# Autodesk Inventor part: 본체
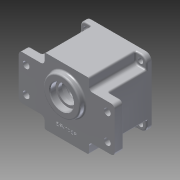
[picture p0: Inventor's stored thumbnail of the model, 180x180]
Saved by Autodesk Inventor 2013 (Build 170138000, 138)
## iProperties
Created: 2015-07
Part Number: 본체
Material: 알루미늄 6061
Document SubType Name: Modeling
Designer: user
Density: 2.71 g/cm^3
Mass: 700.948 g
Surface Area: 679.373 cm^2
Volume: 258.652 cm^3
Author: user
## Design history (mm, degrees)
sketch "스케치1"
  geometry: L1 (65, -30)-(65, 30); L2 (-65, 30)-(-65, -30); L3 (-30, 45)-(30, 45); L4 (30, -45)-(-30, -45); L5 (65, 30)-(35, 30); L6 (-35, 30)-(-65, 30); L7 (30, 45)-(30, 35); L8 (30, -35)-(30, -45); L9 (-30, -45)-(-30, -35); L10 (-30, 35)-(-30, 45); L11 (-65, -30)-(-35, -30); L12 (35, -30)-(65, -30); A1 r 5 centre (35, 35) between (30, 35) and (35, 30); A2 r 5 centre (35, -35) between (35, -30) and (30, -35); A3 r 5 centre (-35, -35) between (-30, -35) and (-35, -30); A4 r 5 centre (-35, 35) between (-35, 30) and (-30, 35); 5 further points
  constraints: 24 end point, 12 tangent, 10 parallel, 8 point on circle, 4 centre point, 4 perpendicular, 3 equal radius, 3 horizontal, 2 horizontal alignment, 2 midpoint, 2 vertical alignment
  dimensions: "d0" = 130 distance of L1.end L2.start; "d2" = 60 distance of L2.start L2.end; "d3" = 60 distance of L3.start L3.end; "d4" = 90 distance of L3.end L4.start; "d5" = 5 radius of A1; "d6" = 35 distance between parallel lines of L1 L8; "d7" = 75 distance between parallel lines of L5 L4; "d8" = 35 distance from line of point (30, 0) L1; "d9" = 60 distance from line of point (0, -30) L5
extrude "돌출1" new body sketch "스케치1" distance "d10" = 12; taper "d11" = 0 deg
sketch "스케치2"
  geometry: L1 (-45, -45)-(45, -45); L2 (45, -45)-(45, 45); L3 (45, 45)-(-45, 45); L4 (-45, 45)-(-45, -45); 3 further points
  constraints: 8 end point, 2 midpoint, 2 parallel, 1 horizontal, 1 horizontal alignment, 1 perpendicular, 1 vertical alignment
  dimensions: "d12" = 90 distance of L3.end L2.end; "d13" = 90 distance of L2.end L1.end
extrude "돌출2" join sketch "스케치2" distance "d14" = 58; taper "d15" = 0 deg
sketch "스케치3"
  geometry: L1 (35, 30)-(45, 30) reference; L2 (45, 45)-(45, 30) reference; L3 (35, 30)-(45, 30) reference; L4 (30, 45)-(30, 35) reference; L5 (-30, 45)-(30, 45) reference; L6 (-30, 35)-(-30, 45) reference; L7 (-45, 30)-(-35, 30) reference; L8 (-45, -30)-(-45, 30) reference; L9 (-45, -30)-(-65, -30) reference; L10 (-65, -30)-(-65, 30) reference; L11 (-65, 30)-(-45, 30) reference; L12 (-45, 30)-(-45, 45) reference; L13 (-45, 45)-(-30, 45) reference; L14 (30, 45)-(45, 45) reference; L15 (45, 30)-(45, -30) reference; L16 (65, -30)-(45, -30) reference; L17 (65, 30)-(65, -30) reference; L18 (45, 30)-(65, 30) reference; L19 (-45, -45)-(-45, -30) reference; L20 (-35, -30)-(-45, -30) reference; L21 (-30, -45)-(-30, -35) reference; L22 (-30, -45)-(-45, -45) reference; L23 (45, -30)-(45, -45) reference; L24 (45, -45)-(30, -45) reference; L25 (30, -45)-(-30, -45) reference; L26 (45, -30)-(35, -30) reference; L27 (30, -35)-(30, -45) reference; A1 r 5 centre (35, 35) between (30, 35) and (35, 30) reference; A2 r 5 centre (-35, 35) between (-35, 30) and (-30, 35) reference; A3 r 5 centre (-35, -35) between (-30, -35) and (-35, -30) reference; A4 r 5 centre (35, -35) between (35, -30) and (30, -35) reference; 1 further point
extrude "돌출3" cut sketch "스케치3" distance "d16" = 51; taper "d17" = 0 deg
sketch "스케치4"
  geometry: L1 (60, 0)-(60, 63) reference; L2 (60, 63)-(75, 63) reference; L3 (75, 63)-(75, 70) reference; L4 (-15, 70)-(75, 70) reference; L5 (-15, 63)-(-15, 70) reference; L6 (-15, 63)-(0, 63) reference; L7 (0, 0)-(0, 63) reference; L8 (60, 0)-(0, 0) reference; 1 further point
fillet "모깎기1" dims "d18" = 8
fillet "모깎기2" dims "d19" = 5
sketch "스케치5"
  geometry: L1 (65, -25)-(65, 25) reference; L2 (60, 30)-(35, 30) reference; C1 r 4.5 at (55, 17.5); C2 r 4.5 at (-55, 17.5); C3 r 4.5 at (55, -17.5); C4 r 4.5 at (-55, -17.5); 1 further point
  constraints: 4 centre point, 3 equal radius
  dimensions: "d26" = 9 diameter of C1; "d27" = 10 distance from line of C1.centre L1; "d28" = 12.5 distance from line of C1.centre L2; "d29" = 10 distance from line of C3.centre L1; "d30" = 47.5 distance from line of C3.centre L2; "d31" = 120 distance from line of C2.centre L1; "d32" = 12.5 distance from line of C2.centre L2; "d33" = 120 distance from line of C4.centre L1; "d34" = 47.5 distance from line of C4.centre L2
extrude "돌출4" cut sketch "스케치5" stored distance "d35" = 51; taper "d36" = 0 deg
sketch "스케치6"
  geometry: L1 (-30, -35)-(-30, -45) reference; L2 (0, 0)-(0, 11); C1 r 25 at (0, 11); 1 further point
  constraints: 2 end point, 1 centre point, 1 coincident, 1 parallel
  dimensions: "d37" = 11 distance of L2.start L2.end; "d38" = 50 diameter of C1
extrude "돌출5" join sketch "스케치6" distance "d39" = 7; taper "d40" = 0 deg
fillet "모깎기4" dims "d41" = 2
sketch "스케치7"
  geometry: C1 r 23 at (0, 0) reference; 1 further point
hole "구멍1" sketch "스케치7" at (0, 0) diameter "d42" = 25; stored, may be unused: countersink angle "d46" = 90 deg, drill point angle "d48" = 118 deg; dims "d43" = 6, "d44" = 32, "d45" = 8, "d47" = 8
chamfer "모따기1" distance "d49" = 1; stored, may be unused: second distance "d50" = 2, angle "d51" = 45 deg
fillet "모깎기5" dims "d52" = 0.3
fillet "모깎기8" dims "d55" = 2
sketch "스케치8"
  geometry: C1 r 3.5 at (-37, -37); C2 r 3.5 at (37, -37); C3 r 3.5 at (37, 37); C4 r 3.5 at (-37, 37); A1 r 8 centre (-37, 37) between (-37, 45) and (-45, 37) reference; A2 r 8 centre (-37, -37) between (-45, -37) and (-37, -45) reference; A3 r 8 centre (37, -37) between (37, -45) and (45, -37) reference; A4 r 8 centre (37, 37) between (45, 37) and (37, 45) reference; 1 further point
  constraints: 4 centre point, 3 concentric, 2 equal radius, 1 coincident
  dimensions: "d65" = 7 diameter of C1; "d66" = 7 diameter of C2
extrude "돌출6" cut sketch "스케치8" stored distance "d67" = 7; taper "d68" = 0 deg
sketch "스케치9"
  geometry: C1 r 12.5 at (0, -11) reference; C2 r 40 at (0, 0); 1 further point
  constraints: 1 centre point, 1 coincident
  dimensions: "d69" = 80 diameter of C2
extrude "돌출7" cut sketch "스케치9" distance "d70" = 9; taper "d71" = 0 deg
sketch "스케치10"
  geometry: C1 r 12.5 at (0, -11) reference; C2 r 40 at (0, 0) reference; C3 r 39 at (0, 0)
  constraints: 1 centre point, 1 coincident
  dimensions: "d72" = 78 diameter of C3
extrude "돌출8" cut sketch "스케치10" distance "d73" = 52; taper "d74" = 0 deg
node "작업 평면1"
sketch "스케치11"
  geometry: 1 further point
sketch "스케치12"
  geometry: L1 (0, 0)-(-55.97, -55.97); L2 (0, 0)-(-45, 0); L3 (-30, -45)-(-30, -35) reference; L4 (-35, -30)-(-45, -30) reference; L5 (-45, -30)-(-45, 30) reference; L6 (-45, 30)-(-35, 30) reference; L7 (-30, 35)-(-30, 45) reference; L8 (30, -45)-(-30, -45) reference; L9 (-30, 45)-(30, 45) reference; L10 (30, 45)-(30, 35) reference; L11 (30, -35)-(30, -45) reference; L12 (35, 30)-(45, 30) reference; L13 (45, 30)-(45, -30) reference; L14 (45, -30)-(35, -30) reference; C1 r 39 at (0, 0) reference; C2 r 40 at (0, 0) reference; C3 r 39 at (0, 0) reference; C4 r 40 at (0, 0) reference; C5 r 4 at (24.749, -24.749); C6 r 4 at (24.749, 24.749); C7 r 4 at (-24.749, 24.749); A1 r 4 centre (-24.749, -24.749) between (-21.809, -27.462) and (-27.462, -21.809); A2 r 39 centre (0, 0) between (-21.134, -32.777) and (-32.777, -21.134); A3 r 3.5 centre (-19.238, -29.836) between (-21.809, -27.462) and (-21.134, -32.777); A4 r 3.5 centre (-29.836, -19.238) between (-32.777, -21.134) and (-27.462, -21.809); A5 r 5 centre (-35, -35) between (-30, -35) and (-35, -30) reference; A6 r 5 centre (-35, 35) between (-35, 30) and (-30, 35) reference; A7 r 5 centre (35, 35) between (30, 35) and (35, 30) reference; A8 r 5 centre (35, -35) between (35, -30) and (30, -35) reference
  constraints: 8 point on circle, 7 centre point, 5 tangent, 4 end point, 1 coincident, 1 point on line, 9 other
  dimensions: "d75" = 45 deg angle of L2 L1; "d77" = 8 diameter of A1; "d80" = 360 deg dimension on C1.centre A1.centre (derived); "d83" = 49.49747 distance of C5.centre C6.centre; "d85" = 7 diameter of A3; "d87" = 7 diameter of A4
extrude "돌출9" join sketch "스케치12" stored distance "d88" = 52; taper "d89" = 0 deg
sketch "스케치13"
  geometry: A1 r 4 centre (-24.749, -24.749) between (-21.809, -27.462) and (-27.462, -21.809) reference; A2 r 4 centre (-24.749, 24.749) between (-27.462, 21.809) and (-21.809, 27.462) reference; A3 r 4 centre (24.749, 24.749) between (21.809, 27.462) and (27.462, 21.809) reference; A4 r 4 centre (24.749, -24.749) between (27.462, -21.809) and (21.809, -27.462) reference
hole "구멍2" sketch "스케치13" at (24.749, 24.749), (24.749, -24.749), (-24.749, -24.749), (-24.749, 24.749) diameter "d93" = 3.459; stored, may be unused: countersink angle "d97" = 90 deg, drill point angle "d99" = 118 deg; dims "d94" = 12, "d95" = 32, "d96" = 8, "d98" = 15
sketch "스케치14"
  geometry: L1 (-60, 30)-(-35, 30) reference; L2 (-30, 35)-(-30, 45) reference; L3 (30, 45)-(30, 35) reference; L4 (35, 30)-(60, 30) reference; L5 (65, 25)-(65, -25) reference; L6 (60, -30)-(35, -30) reference; L7 (30, -35)-(30, -45) reference; L8 (-30, -45)-(-30, -35) reference; L9 (-35, -30)-(-60, -30) reference; L10 (-65, -25)-(-65, 25) reference; L11 (30, -45)-(-30, -45) reference; L12 (-30, 45)-(30, 45) reference; C1 r 12.5 at (0, -11) reference; C2 r 12.5 at (0, -11) reference; C3 r 4.5 at (55, 17.5) reference; C4 r 4.5 at (55, -17.5) reference; C5 r 4.5 at (-55, -17.5) reference; C6 r 4.5 at (-55, 17.5) reference; C7 r 20.5 at (0, -11); A1 r 4 centre (-24.749, -24.749) between (-21.809, -27.462) and (-27.462, -21.809) reference; A2 r 3.5 centre (-19.238, -29.836) between (-21.809, -27.462) and (-21.134, -32.777) reference; A3 r 39 centre (0, 0) between (-21.134, -32.777) and (21.134, -32.777) reference; A4 r 3.5 centre (19.238, -29.836) between (21.134, -32.777) and (21.809, -27.462) reference; A5 r 4 centre (24.749, -24.749) between (27.462, -21.809) and (21.809, -27.462) reference; A6 r 3.5 centre (29.836, -19.238) between (27.462, -21.809) and (32.777, -21.134) reference; A7 r 39 centre (0, 0) between (32.777, -21.134) and (32.777, 21.134) reference; A8 r 3.5 centre (29.836, 19.238) between (32.777, 21.134) and (27.462, 21.809) reference; A9 r 4 centre (24.749, 24.749) between (21.809, 27.462) and (27.462, 21.809) reference; A10 r 3.5 centre (19.238, 29.836) between (21.809, 27.462) and (21.134, 32.777) reference; A11 r 39 centre (0, 0) between (21.134, 32.777) and (-21.134, 32.777) reference; A12 r 3.5 centre (-19.238, 29.836) between (-21.134, 32.777) and (-21.809, 27.462) reference; A13 r 4 centre (-24.749, 24.749) between (-27.462, 21.809) and (-21.809, 27.462) reference; A14 r 3.5 centre (-29.836, 19.238) between (-27.462, 21.809) and (-32.777, 21.134) reference; A15 r 39 centre (0, 0) between (-32.777, 21.134) and (-32.777, -21.134) reference; A16 r 3.5 centre (-29.836, -19.238) between (-32.777, -21.134) and (-27.462, -21.809) reference; A17 r 5 centre (-60, 25) between (-60, 30) and (-65, 25) reference; A18 r 5 centre (-35, 35) between (-35, 30) and (-30, 35) reference; A19 r 5 centre (35, 35) between (30, 35) and (35, 30) reference; A20 r 5 centre (60, 25) between (65, 25) and (60, 30) reference; A21 r 5 centre (60, -25) between (60, -30) and (65, -25) reference; A22 r 5 centre (35, -35) between (35, -30) and (30, -35) reference; A23 r 5 centre (-35, -35) between (-30, -35) and (-35, -30) reference; A24 r 5 centre (-60, -25) between (-65, -25) and (-60, -30) reference
  constraints: 1 centre point, 1 coincident
  dimensions: "d100" = 41 diameter of C7
extrude "돌출10" join sketch "스케치14" distance "d101" = 7; taper "d102" = 0 deg
sketch "스케치15"
  geometry: L1 (-60, 30)-(-35, 30) reference; L2 (-30, 35)-(-30, 45) reference; L3 (30, 45)-(30, 35) reference; L4 (35, 30)-(60, 30) reference; L5 (65, 25)-(65, -25) reference; L6 (60, -30)-(35, -30) reference; L7 (30, -35)-(30, -45) reference; L8 (-30, -45)-(-30, -35) reference; L9 (-35, -30)-(-60, -30) reference; L10 (-65, -25)-(-65, 25) reference; L11 (0, 0)-(0, 20); L12 (30, -45)-(-30, -45) reference; L13 (-30, 45)-(30, 45) reference; C1 r 20.5 at (0, -11) reference; C2 r 12.5 at (0, -11) reference; C3 r 4.5 at (55, 17.5) reference; C4 r 4.5 at (55, -17.5) reference; C5 r 4.5 at (-55, -17.5) reference; C6 r 4.5 at (-55, 17.5) reference; C7 r 14 at (0, 20); A1 r 4 centre (-24.749, -24.749) between (-21.809, -27.462) and (-27.462, -21.809) reference; A2 r 3.5 centre (-19.238, -29.836) between (-21.809, -27.462) and (-21.134, -32.777) reference; A3 r 39 centre (0, 0) between (-21.134, -32.777) and (21.134, -32.777) reference; A4 r 3.5 centre (19.238, -29.836) between (21.134, -32.777) and (21.809, -27.462) reference; A5 r 4 centre (24.749, -24.749) between (27.462, -21.809) and (21.809, -27.462) reference; A6 r 3.5 centre (29.836, -19.238) between (27.462, -21.809) and (32.777, -21.134) reference; A7 r 39 centre (0, 0) between (32.777, -21.134) and (32.777, 21.134) reference; A8 r 3.5 centre (29.836, 19.238) between (32.777, 21.134) and (27.462, 21.809) reference; A9 r 4 centre (24.749, 24.749) between (21.809, 27.462) and (27.462, 21.809) reference; A10 r 3.5 centre (19.238, 29.836) between (21.809, 27.462) and (21.134, 32.777) reference; A11 r 39 centre (0, 0) between (21.134, 32.777) and (-21.134, 32.777) reference; A12 r 3.5 centre (-19.238, 29.836) between (-21.134, 32.777) and (-21.809, 27.462) reference; A13 r 4 centre (-24.749, 24.749) between (-27.462, 21.809) and (-21.809, 27.462) reference; A14 r 3.5 centre (-29.836, 19.238) between (-27.462, 21.809) and (-32.777, 21.134) reference; A15 r 39 centre (0, 0) between (-32.777, 21.134) and (-32.777, -21.134) reference; A16 r 3.5 centre (-29.836, -19.238) between (-32.777, -21.134) and (-27.462, -21.809) reference; A17 r 5 centre (-60, 25) between (-60, 30) and (-65, 25) reference; A18 r 5 centre (-35, 35) between (-35, 30) and (-30, 35) reference; A19 r 5 centre (35, 35) between (30, 35) and (35, 30) reference; A20 r 5 centre (60, 25) between (65, 25) and (60, 30) reference; A21 r 5 centre (60, -25) between (60, -30) and (65, -25) reference; A22 r 5 centre (35, -35) between (35, -30) and (30, -35) reference; A23 r 5 centre (-35, -35) between (-30, -35) and (-35, -30) reference; A24 r 5 centre (-60, -25) between (-65, -25) and (-60, -30) reference
  constraints: 2 end point, 1 centre point, 1 coincident, 1 parallel
  dimensions: "d103" = 20 distance of L11.start L11.end; "d104" = 28 diameter of C7
extrude "돌출11" join sketch "스케치15" distance "d105" = 7; taper "d106" = 0 deg
fillet "모깎기9" dims "d107" = 3
fillet "모깎기10" dims "d108" = 2
fillet "모깎기11" dims "d109" = 2
sketch "스케치16"
  geometry: C1 r 12.5 at (0, -11) reference; A1 r 20.5 centre (0, -11) between (-11.115, 6.225) and (11.115, 6.225) reference; A2 r 3 centre (12.742, 8.746) between (10.493, 10.732) and (11.115, 6.225) reference; A3 r 14 centre (0, 20) between (10.493, 10.732) and (-10.493, 10.732) reference; A4 r 3 centre (-12.742, 8.746) between (-11.115, 6.225) and (-10.493, 10.732) reference; 1 further point
sketch "스케치17"
  geometry: A1 r 20.5 centre (0, -11) between (-11.115, 6.225) and (11.115, 6.225) reference; 1 further point
hole "구멍3" sketch "스케치17" at (0, -11) diameter "d110" = 25; stored, may be unused: countersink angle "d114" = 90 deg, drill point angle "d116" = 118 deg; dims "d111" = 6, "d112" = 35, "d113" = 10, "d115" = 8
fillet "모깎기12" dims "d117" = 0.3
chamfer "모따기2" distance "d118" = 1; stored, may be unused: second distance "d119" = 2, angle "d120" = 45 deg
sketch "스케치18"
  geometry: A1 r 14 centre (0, 20) between (10.493, 10.732) and (-10.493, 10.732) reference; 1 further point
hole "구멍4" sketch "스케치18" at (0, 20) diameter "d121" = 22; stored, may be unused: countersink angle "d125" = 90 deg, drill point angle "d127" = 0 deg; dims "d122" = 6, "d123" = 35, "d124" = 10, "d126" = 7
sketch "스케치19"
  geometry: C1 r 11 at (0, 0) reference; 1 further point
hole "구멍5" sketch "스케치19" at (0, 0) diameter "d128" = 19; stored, may be unused: countersink angle "d132" = 90 deg, drill point angle "d134" = 0 deg; dims "d129" = 6, "d130" = 35, "d131" = 10, "d133" = 1
fillet "모깎기13" dims "d135" = 1
sketch "스케치20"
  geometry: 1 further point
chamfer "모따기3" distance "d136" = 1; stored, may be unused: second distance "d137" = 2, angle "d138" = 45 deg
sketch "스케치21"
  geometry: L1 (-30, -45)-(30, -45) reference; L2 (-30, -35)-(-30, -45) reference; L3 (0, -45)-(0, -30); 5 further points
  constraints: 2 end point, 1 coincident, 1 midpoint, 1 parallel, 1 other
  dimensions: "d139" = 15 distance of L3.start L3.end
feature "엠보싱1" sketch "스케치21" dims "d0" = 130, "d2" = 60, "d3" = 60, "d4" = 90, "d5" = 5, "d6" = 35, "d7" = 75, "d8" = 35, "d9" = 60, "d140" = 0.5, "d141" = 0
sketch "스케치22"
  geometry: C1 r 1.73 at (-24.749, -24.749) reference; C2 r 1.73 at (24.749, 24.749) reference; C3 r 1.73 at (24.749, -24.749) reference; C4 r 1.73 at (-24.749, 24.749) reference; C5 r 40 at (0, 0) reference; A1 r 3.5 centre (-19.238, -29.836) between (-21.809, -27.462) and (-21.134, -32.777) reference; A2 r 4 centre (-24.749, -24.749) between (-21.809, -27.462) and (-27.462, -21.809) reference; A3 r 3.5 centre (-29.836, -19.238) between (-32.777, -21.134) and (-27.462, -21.809) reference; A4 r 39 centre (0, 0) between (-32.777, 21.134) and (-32.777, -21.134) reference; A5 r 3.5 centre (-29.836, 19.238) between (-27.462, 21.809) and (-32.777, 21.134) reference; A6 r 4 centre (-24.749, 24.749) between (-27.462, 21.809) and (-21.809, 27.462) reference; A7 r 3.5 centre (-19.238, 29.836) between (-21.134, 32.777) and (-21.809, 27.462) reference; A8 r 39 centre (0, 0) between (21.134, 32.777) and (-21.134, 32.777) reference; A9 r 3.5 centre (19.238, 29.836) between (21.809, 27.462) and (21.134, 32.777) reference; A10 r 4 centre (24.749, 24.749) between (21.809, 27.462) and (27.462, 21.809) reference; A11 r 3.5 centre (29.836, 19.238) between (32.777, 21.134) and (27.462, 21.809) reference; A12 r 39 centre (0, 0) between (32.777, -21.134) and (32.777, 21.134) reference; A13 r 3.5 centre (29.836, -19.238) between (27.462, -21.809) and (32.777, -21.134) reference; A14 r 4 centre (24.749, -24.749) between (27.462, -21.809) and (21.809, -27.462) reference; A15 r 3.5 centre (19.238, -29.836) between (21.134, -32.777) and (21.809, -27.462) reference; A16 r 39 centre (0, 0) between (-21.134, -32.777) and (21.134, -32.777) reference
fillet "모깎기16" dims "d144" = 2
fillet "모깎기17" dims "d145" = 2
fillet "모깎기18" dims "d146" = 2
fillet "모깎기19" dims "d147" = 2
fillet "모깎기20" dims "d148" = 2
fillet "모깎기21" dims "d149" = 2
fillet "모깎기22" dims "d150" = 2
fillet "모깎기23" dims "d151" = 2
fillet "모깎기24" dims "d152" = 2
fillet "모깎기25" dims "d153" = 0.3
node "솔리드1"
pattern_circular "원형 패턴1" dims angle "d91" = 360 deg
node "절단 모서리 투영1"
node "절단 모서리 투영2"
node "절단 모서리 투영3"
node "절단 모서리 투영4"
